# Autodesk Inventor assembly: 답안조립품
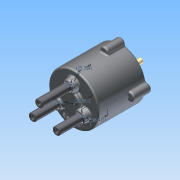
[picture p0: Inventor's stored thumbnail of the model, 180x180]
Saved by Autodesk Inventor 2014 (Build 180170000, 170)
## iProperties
Created: 2015-09
Part Number: 답안조립품
Document SubType Name: Assembly
Designer: study
Mass: 2160.14 g
Surface Area: 1801.25 cm^2
Volume: 438.509 cm^3
Density: 4.92611 g/cm^3
Author: study
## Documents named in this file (14)
- C:\Users\study\Desktop\350916V1002\답안조립품.iam
- C:\Users\study\Desktop\350916V1002\몸체.ipt
- C:\Users\study\Desktop\350916V1002\메인 축.ipt
- C:\Users\study\Desktop\350916V1002\판캠.ipt
- C:\Users\study\Desktop\350916V1002\슬라이드 축.ipt
- C:\Users\study\Desktop\350916V1002\멈춤링 22 x 1.2.ipt
- C:\Users\study\Desktop\350916V1002\멈춤링 10 x 1.ipt
- C:\Users\study\Desktop\350916V1002\커버.ipt
- C:\Users\study\Desktop\350916V1002\베어링 NA 4900.ipt
- C:\Users\study\Desktop\350916V1002\오일실.ipt
- C:\Users\study\Desktop\350916V1002\M5x0.8x20.ipt
- C:\Users\study\Desktop\350916V1002\11-스프링.ipt
- C:\Users\study\Desktop\350916V1002\12-스프링.ipt
- C:\Users\study\Desktop\350916V1002\13-스프링.ipt
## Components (7 placed, 4 different names)
1. 11-스프링:1
2. 12-스프링:1
3. 13-스프링:1
4. M5x0.8x20:1
5. M5x0.8x20:2
6. M5x0.8x20:3
7. M5x0.8x20:4
